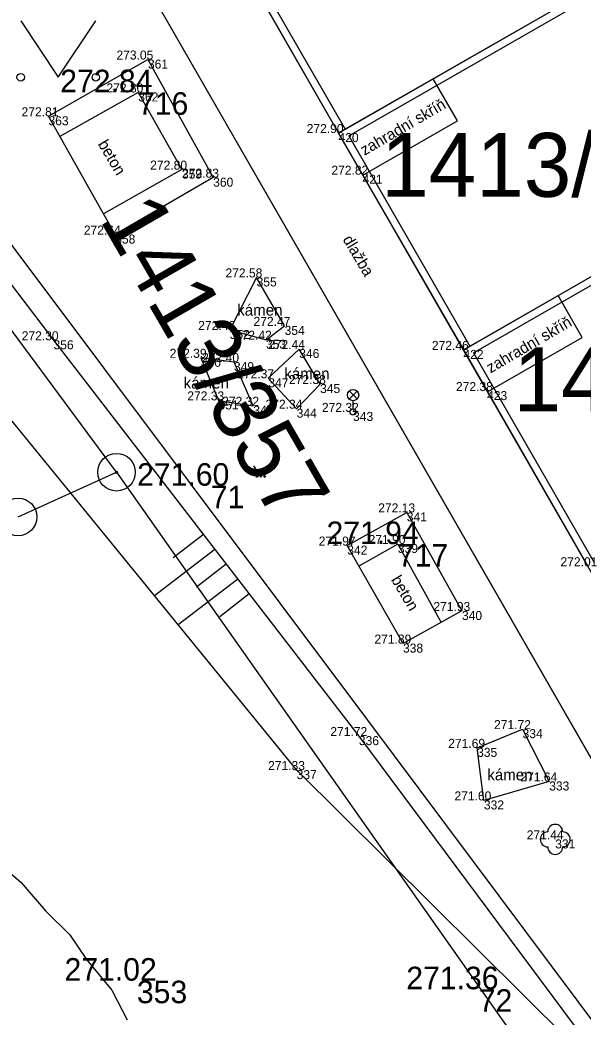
# Model space of a CAD drawing. Extents: x -771260 to -770828, y -1053564 to -1052811.
# Drawn here: x -770977.14 to -770962.16, y -1053224.04 to -1053197.5 of the extents above; entities that cross this region are included whole.
import ezdxf

# ---------------------------------------------------------------- set-up
doc = ezdxf.new("R2010")
doc.units = 0
for name, color, linetype in [('25_10_2019_beton', 7, 'Continuous'), ('25_10_2019_dlazba', 7, 'Continuous'), ('25_10_2019_hrana', 7, 'Continuous'), ('25_10_2019_kameny', 7, 'Continuous'), ('25_10_2019_lampa', 7, 'Continuous'), ('25_10_2019_operna_stena', 7, 'Continuous'), ('25_10_2019_pata', 7, 'Continuous'), ('25_10_2019_popis_objektu', 7, 'Continuous'), ('25_10_2019_popis_povrchu', 7, 'Continuous'), ('25_10_2019_srafy', 7, 'Continuous'), ('25_10_2019_strom', 7, 'Continuous'), ('25_10_2019_zahradni_skrin', 7, 'Continuous'), ('25_10_2019_zamereny_bod', 7, 'Continuous'), ('25_10_2019_zamereny_bod_cislo', 7, 'Continuous'), ('25_10_2019_zamereny_bod_vyska', 7, 'Continuous'), ('25_10_2019_znacka_zelen', 7, 'Continuous'), ('25_3_2019_vrstevnice_interval_po_1m', 7, 'Continuous'), ('25_3_2019_zamereny_bod', 7, 'Continuous'), ('25_3_2019_zamereny_bod_cislo', 7, 'Continuous'), ('25_3_2019_zamereny_bod_vyska', 7, 'Continuous'), ('6_8_2021_zamereny_bod', 7, 'Continuous'), ('6_8_2021_zamereny_bod_cislo', 7, 'Continuous'), ('6_8_2021_zamereny_bod_vyska', 7, 'Continuous'), ('Default', 7, 'Continuous'), ('DKM_Hranice parcel', 7, 'Continuous'), ('DKM_Parcelní čísla', 7, 'Continuous'), ('DKM_Značky bodu BP', 7, 'Continuous'), ('DKM_Značky kultur', 7, 'Continuous')]:
    doc.layers.add(name, color=color, linetype=linetype)

# ---------------------------------------------------------------- blocks, each defined once
blk = doc.blocks.new('POINT_DISPLAY')
at = {"layer": 'Default'}
blk.add_line((0, 0), (0, 0), dxfattribs=at)
blk = doc.blocks.new('6.560')
at = {"layer": '25_10_2019_lampa'}
for p, q in [((-5.3, 17.2), (5.3, 27.8)), ((5.4, 17.3), (-5.1, 27.9)), ((0, 4), (0, 15))]:
    blk.add_line(p, q, dxfattribs=at)
for centre, radius in [((0, 22.5), 7.5), ((0, 0), 4), ((0, 0), 4)]:
    blk.add_circle(centre, radius, dxfattribs=at)
blk = doc.blocks.new('3.130')
at = {"layer": '25_10_2019_strom'}
blk.add_circle((0, 0), 0.01, dxfattribs=at)
for centre, start, end in [((0, 10), 0, 180), ((-10, 0), 90, 270), ((10, 0), 270, 90), ((0, -10), 180, 360)]:
    blk.add_arc(centre, 10, start, end, dxfattribs=at)
blk = doc.blocks.new('3.140')
at = {"layer": '25_10_2019_znacka_zelen'}
blk.add_lwpolyline([(-10, 15), (0, 0), (10, 15)], dxfattribs=at)
for centre in [(-5, 1), (-5, 1), (5, 1), (5, 1)]:
    blk.add_circle(centre, 1, dxfattribs=at)

msp = doc.modelspace()

# ---------------------------------------------------------------- linework, layer by layer
at = {"layer": '25_10_2019_beton'}
for p, q in [((-770976.38, -1053200.066), (-770973.734, -1053198.556)), ((-770973.734, -1053198.556), (-770971.997, -1053201.7)), ((-770973.992, -1053199.433), (-770976.075, -1053200.608)), ((-770973.992, -1053199.433), (-770972.828, -1053201.486)), ((-770974.604, -1053203.214), (-770976.38, -1053200.066)), ((-770972.828, -1053201.486), (-770974.915, -1053202.663)), ((-770971.997, -1053201.7), (-770974.604, -1053203.214)), ((-770968.429, -1053211.493), (-770966.845, -1053210.609)), ((-770966.845, -1053210.609), (-770965.378, -1053213.232)), ((-770966.947, -1053214.1), (-770968.429, -1053211.493)), ((-770967.083, -1053211.451), (-770968.118, -1053212.04)), ((-770967.083, -1053211.451), (-770965.929, -1053213.537)), ((-770965.378, -1053213.232), (-770966.947, -1053214.1))]:
    msp.add_line(p, q, dxfattribs=at)
at = {"layer": '25_10_2019_dlazba'}
msp.add_line((-770977.395, -1053190.28), (-770957.487, -1053224.903), dxfattribs=at)
at = {"layer": '25_10_2019_hrana'}
for p, q in [((-770984.397, -1053195.344), (-770976.246, -1053206.028)), ((-770976.246, -1053206.028), (-770968.12, -1053216.563)), ((-770968.12, -1053216.563), (-770960.882, -1053226.288))]:
    msp.add_line(p, q, dxfattribs=at)
at = {"layer": '25_10_2019_kameny'}
for p, q in [((-770970.842, -1053204.355), (-770971.557, -1053205.754)), ((-770970.096, -1053205.645), (-770970.842, -1053204.355)), ((-770970.592, -1053206.014), (-770970.096, -1053205.645)), ((-770971.557, -1053205.754), (-770970.592, -1053206.014)), ((-770969.707, -1053206.261), (-770970.532, -1053207.04)), ((-770969.153, -1053207.192), (-770969.707, -1053206.261)), ((-770971.444, -1053206.609), (-770972.325, -1053206.495)), ((-770972.325, -1053206.495), (-770971.858, -1053207.628)), ((-770970.93, -1053207.773), (-770971.444, -1053206.609)), ((-770970.532, -1053207.04), (-770969.777, -1053207.849)), ((-770969.777, -1053207.849), (-770969.153, -1053207.192)), ((-770971.858, -1053207.628), (-770970.93, -1053207.773)), ((-770964.975, -1053216.875), (-770963.764, -1053216.378)), ((-770963.764, -1053216.378), (-770963.056, -1053217.77)), ((-770964.794, -1053218.275), (-770964.975, -1053216.875)), ((-770963.056, -1053217.77), (-770964.794, -1053218.275))]:
    msp.add_line(p, q, dxfattribs=at)
at = {"layer": '25_10_2019_operna_stena'}
for p, q in [((-770975.283, -1053188.99), (-770955.348, -1053223.679)), ((-770968.662, -1053200.513), (-770956.797, -1053193.705)), ((-770968.388, -1053200.586), (-770956.697, -1053193.879)), ((-770971.697, -1053194.827), (-770968.487, -1053200.413)), ((-770965.339, -1053206.284), (-770953.496, -1053199.466)), ((-770965.069, -1053206.36), (-770953.397, -1053199.639)), ((-770968.388, -1053200.586), (-770965.169, -1053206.186)), ((-770965.069, -1053206.36), (-770961.86, -1053211.945))]:
    msp.add_line(p, q, dxfattribs=at)
at = {"layer": '25_10_2019_pata'}
for p, q in [((-770969.776, -1053217.468), (-770978.37, -1053206.93)), ((-770960.882, -1053226.288), (-770969.776, -1053217.468))]:
    msp.add_line(p, q, dxfattribs=at)
at = {"layer": '25_10_2019_srafy'}
for p, q in [((-770972.259, -1053211.197), (-770973.067, -1053211.82)), ((-770971.954, -1053211.593), (-770973.558, -1053212.83)), ((-770971.649, -1053211.989), (-770972.445, -1053212.603)), ((-770971.343, -1053212.385), (-770972.926, -1053213.606)), ((-770971.038, -1053212.781), (-770971.824, -1053213.387))]:
    msp.add_line(p, q, dxfattribs=at)
at = {"layer": '25_10_2019_zahradni_skrin'}
for p, q in [((-770965.495, -1053200.186), (-770966.14, -1053199.066)), ((-770968.015, -1053201.636), (-770965.495, -1053200.186)), ((-770962.179, -1053205.95), (-770962.821, -1053204.835)), ((-770964.702, -1053207.402), (-770962.179, -1053205.95))]:
    msp.add_line(p, q, dxfattribs=at)
at = {"layer": '25_3_2019_vrstevnice_interval_po_1m'}
for points in [[(-770977.59, -1053220.041), (-770977.106, -1053220.455), (-770976.458, -1053221.21), (-770975.809, -1053221.853), (-770975.369, -1053222.507), (-770974.692, -1053223.325), (-770974.684, -1053223.341), (-770974.283, -1053224.114)], [(-770977.106, -1053220.455), (-770977.106, -1053220.455)], [(-770976.458, -1053221.21), (-770976.458, -1053221.21)], [(-770975.809, -1053221.853), (-770975.809, -1053221.853)], [(-770975.369, -1053222.507), (-770975.369, -1053222.507)], [(-770974.692, -1053223.325), (-770974.692, -1053223.325)]]:
    msp.add_lwpolyline(points, dxfattribs=at)
at = {"layer": 'DKM_Hranice parcel'}
for p, q in [((-770968.66, -1053200.51), (-770971.96, -1053194.75)), ((-770968.66, -1053200.51), (-770958.9, -1053194.91)), ((-770965.33, -1053206.28), (-770968.66, -1053200.51)), ((-770965.33, -1053206.28), (-770955.59, -1053200.67)), ((-770962.02, -1053212.05), (-770965.33, -1053206.28)), ((-770977.19, -1053210.73), (-770974.57, -1053209.54))]:
    msp.add_line(p, q, dxfattribs=at)
for points in [[(-770974.57, -1053209.54), (-770987.64, -1053191.87), (-770995.02, -1053183.77), (-771005.13, -1053169.12)], [(-770984.27, -1053194.26), (-770977.39, -1053190.28), (-770957.49, -1053224.9), (-770960.18, -1053226.44)], [(-770960.18, -1053226.44), (-770967.88, -1053216.14), (-770984.27, -1053194.26)], [(-770974.57, -1053209.54), (-770953.18, -1053239.92), (-770951.58, -1053241.72)]]:
    msp.add_lwpolyline(points, dxfattribs=at)
at = {"layer": 'DKM_Značky bodu BP'}
for centre, radius in [((-770974.57, -1053209.54), 0.5), ((-770974.57, -1053209.54), 0.0303), ((-770977.19, -1053210.73), 0.5)]:
    msp.add_circle(centre, radius, dxfattribs=at)
at = {"layer": 'DKM_Značky kultur'}
msp.add_lwpolyline([(-770977.12, -1053197.529), (-770976.12, -1053199.03), (-770975.12, -1053197.529)], dxfattribs=at)
for centre in [(-770977.12, -1053199.029), (-770975.12, -1053199.029)]:
    msp.add_circle(centre, 0.1, dxfattribs=at)

# ---------------------------------------------------------------- block references
at = {"layer": '25_10_2019_lampa', "xscale": 0.020000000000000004, "yscale": 0.020000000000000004}
msp.add_blockref('6.560', (-770968.276, -1053207.936), dxfattribs=at)
at = {"layer": '25_10_2019_strom', "xscale": 0.020000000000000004, "yscale": 0.020000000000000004}
msp.add_blockref('3.130', (-770962.896, -1053219.312), dxfattribs=at)
at = {"layer": '25_10_2019_zamereny_bod', "xscale": 0.1, "yscale": 0.10000000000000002}
for p in [(-770973.734, -1053198.557), (-770973.992, -1053199.433), (-770976.381, -1053200.067), (-770968.663, -1053200.513), (-770972.828, -1053201.486), (-770971.998, -1053201.7), (-770968.024, -1053201.622), (-770974.605, -1053203.215), (-770970.843, -1053204.356), (-770970.097, -1053205.645), (-770971.557, -1053205.754), (-770976.247, -1053206.029), (-770970.593, -1053206.015), (-770969.708, -1053206.261), (-770972.326, -1053206.495), (-770965.339, -1053206.285), (-770971.445, -1053206.61), (-770970.532, -1053207.04), (-770969.154, -1053207.193), (-770964.71, -1053207.381), (-770971.859, -1053207.628), (-770970.931, -1053207.773), (-770969.777, -1053207.849), (-770968.276, -1053207.936), (-770966.846, -1053210.609), (-770968.43, -1053211.493), (-770967.083, -1053211.451), (-770965.378, -1053213.233), (-770966.947, -1053214.101), (-770968.121, -1053216.563), (-770963.765, -1053216.378), (-770964.976, -1053216.876), (-770969.777, -1053217.468), (-770963.057, -1053217.77), (-770964.794, -1053218.275), (-770962.896, -1053219.312)]:
    msp.add_blockref('POINT_DISPLAY', p, dxfattribs=at)
at = {"layer": '25_10_2019_znacka_zelen', "xscale": 0.020000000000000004, "yscale": 0.020000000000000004}
msp.add_blockref('3.140', (-770970.729, -1053209.673), dxfattribs=at)
at = {"layer": '25_3_2019_zamereny_bod', "xscale": 0.1, "yscale": 0.10000000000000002}
for p in [(-770972.061, -1053209.899), (-770974.028, -1053223.072), (-770964.932, -1053223.3)]:
    msp.add_blockref('POINT_DISPLAY', p, dxfattribs=at)
at = {"layer": '6_8_2021_zamereny_bod', "xscale": 0.1, "yscale": 0.10000000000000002}
for p in [(-770973.998, -1053199.427), (-770967.082, -1053211.452)]:
    msp.add_blockref('POINT_DISPLAY', p, dxfattribs=at)

# ---------------------------------------------------------------- texts
at = {"layer": '25_10_2019_popis_objektu'}
for p in [(-770967.972, -1053201.121), (-770964.619, -1053206.914)]:
    msp.add_text('zahradní skříň', height=0.3, rotation=30.3604, dxfattribs=at).set_placement(p)
for p in [(-770971.358, -1053205.372), (-770970.106, -1053207.064), (-770972.785, -1053207.311), (-770964.704, -1053217.741)]:
    msp.add_text('kámen', height=0.3, dxfattribs=at).set_placement(p)
at = {"layer": '25_10_2019_popis_povrchu'}
for s, p in [('beton', (-770975.075, -1053200.804)), ('dlažba', (-770968.562, -1053203.343)), ('beton', (-770967.275, -1053212.398))]:
    msp.add_text(s, height=0.3, rotation=300.687, dxfattribs=at).set_placement(p)
at = {"layer": '25_10_2019_zamereny_bod_cislo'}
for s, p in [('361', (-770973.734, -1053198.797)), ('362', (-770973.992, -1053199.673)), ('363', (-770976.381, -1053200.307)), ('420', (-770968.663, -1053200.753)), ('359', (-770972.828, -1053201.726)), ('360', (-770971.998, -1053201.94)), ('421', (-770968.024, -1053201.862)), ('358', (-770974.605, -1053203.455)), ('355', (-770970.843, -1053204.596)), ('354', (-770970.097, -1053205.885)), ('352', (-770971.557, -1053205.994)), ('356', (-770976.247, -1053206.269)), ('353', (-770970.593, -1053206.255)), ('346', (-770969.708, -1053206.501)), ('350', (-770972.326, -1053206.735)), ('422', (-770965.339, -1053206.525)), ('349', (-770971.445, -1053206.85)), ('347', (-770970.532, -1053207.28)), ('345', (-770969.154, -1053207.433)), ('423', (-770964.71, -1053207.621)), ('351', (-770971.859, -1053207.868)), ('348', (-770970.931, -1053208.013)), ('344', (-770969.777, -1053208.089)), ('343', (-770968.276, -1053208.176)), ('341', (-770966.846, -1053210.849)), ('342', (-770968.43, -1053211.733)), ('339', (-770967.083, -1053211.691)), ('340', (-770965.378, -1053213.473)), ('338', (-770966.947, -1053214.341)), ('336', (-770968.121, -1053216.803)), ('334', (-770963.765, -1053216.618)), ('335', (-770964.976, -1053217.116)), ('337', (-770969.777, -1053217.708)), ('333', (-770963.057, -1053218.01)), ('332', (-770964.794, -1053218.515)), ('331', (-770962.896, -1053219.552))]:
    msp.add_text(s, height=0.24, dxfattribs=at).set_placement(p)
at = {"layer": '25_10_2019_zamereny_bod_vyska'}
for s, p in [('273.05 ', (-770974.572, -1053198.557)), ('272.80 ', (-770974.838, -1053199.433)), ('272.81 ', (-770977.096, -1053200.067)), ('272.90 ', (-770969.51, -1053200.513)), ('272.80 ', (-770973.674, -1053201.486)), ('272.83 ', (-770972.826, -1053201.7)), ('272.82 ', (-770968.852, -1053201.622)), ('272.64 ', (-770975.44, -1053203.215)), ('272.58 ', (-770971.671, -1053204.356)), ('272.47 ', (-770970.924, -1053205.645)), ('272.46 ', (-770972.396, -1053205.754)), ('272.30 ', (-770977.093, -1053206.029)), ('272.42 ', (-770971.421, -1053206.015)), ('272.39 ', (-770973.155, -1053206.495)), ('272.44 ', (-770970.536, -1053206.261)), ('272.46 ', (-770966.178, -1053206.285)), ('272.40 ', (-770972.291, -1053206.61)), ('272.37 ', (-770971.359, -1053207.04)), ('272.38 ', (-770969.982, -1053207.193)), ('272.38 ', (-770965.538, -1053207.381)), ('272.33 ', (-770972.687, -1053207.628)), ('272.32 ', (-770971.759, -1053207.773)), ('272.34 ', (-770970.605, -1053207.849)), ('272.32 ', (-770969.104, -1053207.936)), ('272.13 ', (-770967.606, -1053210.609)), ('271.97 ', (-770969.19, -1053211.493)), ('271.90 ', (-770967.862, -1053211.451)), ('272.01 ', (-770962.756, -1053212.043)), ('271.93 ', (-770966.139, -1053213.233)), ('271.89 ', (-770967.708, -1053214.101)), ('271.72 ', (-770968.881, -1053216.563)), ('271.72 ', (-770964.525, -1053216.378)), ('271.69 ', (-770965.744, -1053216.876)), ('271.33 ', (-770970.537, -1053217.468)), ('271.64 ', (-770963.824, -1053217.77)), ('271.60 ', (-770965.578, -1053218.275)), ('271.44 ', (-770963.656, -1053219.312))]:
    msp.add_text(s, height=0.24, dxfattribs=at).set_placement(p)
at = {"layer": '25_3_2019_zamereny_bod_cislo'}
for s, p in [('71', (-770972.061, -1053210.499)), ('353', (-770974.028, -1053223.672)), ('72', (-770964.932, -1053223.9))]:
    msp.add_text(s, height=0.6, dxfattribs=at).set_placement(p)
at = {"layer": '25_3_2019_zamereny_bod_vyska'}
for s, p in [('271.60 ', (-770974.022, -1053209.899)), ('271.02 ', (-770975.953, -1053223.072)), ('271.36 ', (-770966.859, -1053223.3))]:
    msp.add_text(s, height=0.6, dxfattribs=at).set_placement(p)
at = {"layer": '6_8_2021_zamereny_bod_cislo'}
for s, p in [('716', (-770973.998, -1053200.027)), ('717', (-770967.082, -1053212.052))]:
    msp.add_text(s, height=0.6, dxfattribs=at).set_placement(p)
at = {"layer": '6_8_2021_zamereny_bod_vyska'}
for s, p in [('272.84 ', (-770976.068, -1053199.427)), ('271.94 ', (-770968.983, -1053211.452))]:
    msp.add_text(s, height=0.6, dxfattribs=at).set_placement(p)
at = {"layer": 'DKM_Parcelní čísla'}
for s, p in [('1413/353', (-770967.525, -1053202.21)), ('1413/354', (-770964.005, -1053207.92))]:
    msp.add_text(s, height=1.7, dxfattribs=at).set_placement(p)
msp.add_text('1413/357', height=1.7, rotation=300, dxfattribs=at).set_placement((-770975.039, -1053202.801))

doc.saveas('drawing.dxf')
